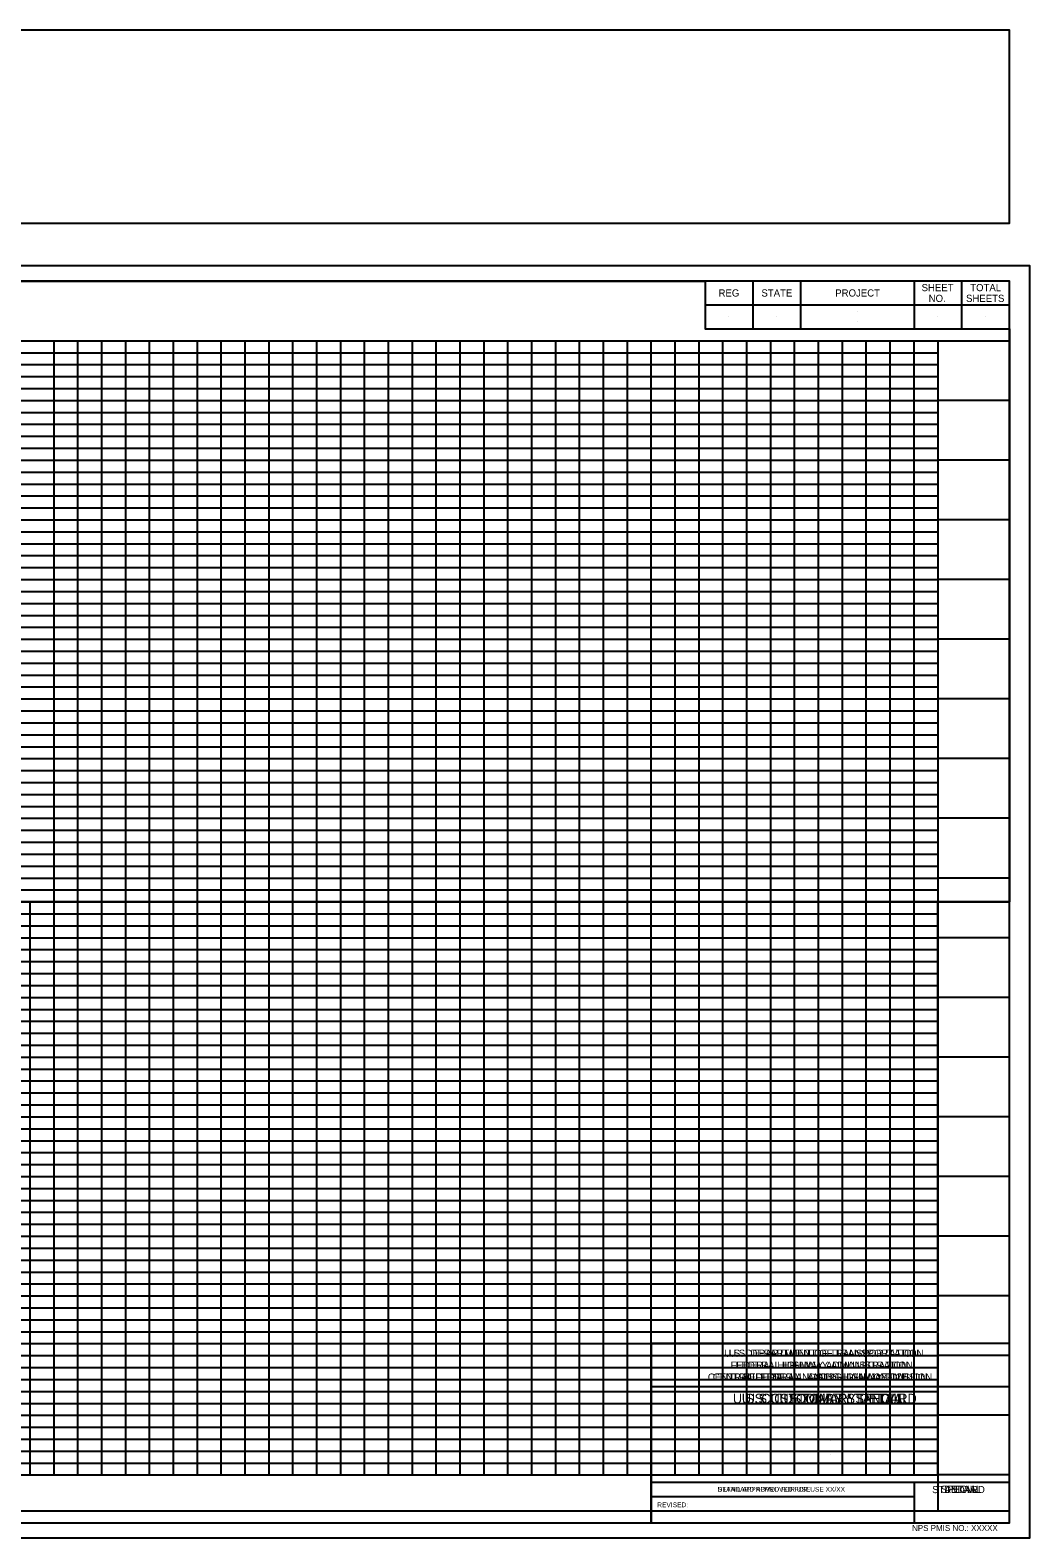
# Model space of a CAD drawing. Extents: x -87 to 1577, y -13 to 1250.
# Drawn here: x 740 to 1577, y -13 to 1250 of the extents above; entities that cross this region are included whole.
import ezdxf

# ---------------------------------------------------------------- set-up
doc = ezdxf.new("R2010")
doc.units = 0
for name, color, linetype in [('D_CFL_Clip_Boundary_1', 7, 'Continuous'), ('D_CFL_Clip_Boundary_2', 7, 'Continuous'), ('D_CFL_Sheet_Border_ PlotShape', 7, 'Continuous'), ('D_CFL_Sheet_Border_Base', 7, 'Continuous'), ('D_CFL_Sheet_Border_Box', 7, 'Continuous'), ('D_CFL_Sheet_Border_Detail', 7, 'Continuous'), ('D_CFL_Sheet_Border_General', 7, 'Continuous'), ('D_CFL_Sheet_Border_NPS_Pkg', 7, 'Continuous'), ('D_CFL_Sheet_Border_Plan_Plan', 7, 'Continuous'), ('D_CFL_Sheet_Border_PnP', 7, 'Continuous'), ('D_CFL_Sheet_Border_Profile', 7, 'Continuous'), ('D_CFL_Sheet_Border_Project_Info', 7, 'Continuous'), ('D_CFL_Sheet_Border_Special', 7, 'Continuous'), ('D_CFL_Sheet_Border_Standard', 7, 'Continuous')]:
    doc.layers.add(name, color=color, linetype=linetype)

msp = doc.modelspace()

# ---------------------------------------------------------------- linework, layer by layer
at = {"layer": 'D_CFL_Clip_Boundary_1'}
msp.add_lwpolyline([(0, 520), (0, 1040), (1305, 1040), (1305, 1000), (1560, 1000), (1560, 520)], close=True, dxfattribs=at)
at = {"layer": 'D_CFL_Clip_Boundary_2'}
msp.add_lwpolyline([(1500, 520), (60, 520), (60, 40), (1500, 40)], close=True, dxfattribs=at)
at = {"layer": 'D_CFL_Sheet_Border_ PlotShape'}
msp.add_line((1576.9, 1052.6), (1576.9, 1052.6), dxfattribs=at)
msp.add_lwpolyline([(-86.9, -12.7), (1576.9, -12.7), (1576.9, 1052.6), (-86.9, 1052.6)], close=True, dxfattribs=at)
at = {"layer": 'D_CFL_Sheet_Border_Base'}
for p, q in [((1345, 1040), (1345, 1000)), ((1385, 1040), (1385, 1000)), ((1480, 1040), (1480, 1000)), ((1520, 1000), (1520, 1040)), ((1305, 1020), (1560, 1020))]:
    msp.add_line(p, q, dxfattribs=at)
for points in [[(362.6, 1088.6), (1560, 1088.6), (1560, 1250.1), (362.6, 1250.1)], [(0, 0), (1560, 0), (1560, 1040), (0, 1040)]]:
    msp.add_lwpolyline(points, close=True, dxfattribs=at)
msp.add_lwpolyline([(1305, 1040), (1305, 1000), (1560, 1000)], dxfattribs=at)
at = {"layer": 'D_CFL_Sheet_Border_Box'}
for p, q in [((1260, 0), (1260, 114)), ((1260, 114), (1560, 114)), ((1410, 57), (1410, 57))]:
    msp.add_line(p, q, dxfattribs=at)
at = {"layer": 'D_CFL_Sheet_Border_Detail'}
for p, q in [((1260, 114), (1560, 114)), ((1410, 69), (1410, 69)), ((1260, 34), (1560, 34)), ((1480, 34), (1480, 0)), ((1260, 22), (1480, 22))]:
    msp.add_line(p, q, dxfattribs=at)
msp.add_lwpolyline([(1560, 150), (1260, 150), (1260, 0)], dxfattribs=at)
at = {"layer": 'D_CFL_Sheet_Border_General'}
for p, q in [((1260, 114), (1560, 114)), ((1410, 57), (1410, 57))]:
    msp.add_line(p, q, dxfattribs=at)
msp.add_lwpolyline([(1560, 150), (1260, 150), (1260, 0)], dxfattribs=at)
at = {"layer": 'D_CFL_Sheet_Border_Plan_Plan'}
for p, q in [((0, 520), (1560, 520)), ((1260, 0), (1260, 114)), ((1260, 114), (1560, 114)), ((1410, 57), (1410, 57))]:
    msp.add_line(p, q, dxfattribs=at)
at = {"layer": 'D_CFL_Sheet_Border_PnP'}
for p, q in [((0, 520), (1560, 520)), ((740, 39.7), (740, 519.7)), ((760, 39.7), (760, 519.7)), ((780, 40), (780, 520)), ((800, 39.7), (800, 519.7)), ((820, 39.7), (820, 519.7)), ((840, 39.7), (840, 519.7)), ((860, 39.7), (860, 519.7)), ((880, 40), (880, 520)), ((900, 39.7), (900, 519.7)), ((920, 39.7), (920, 519.7)), ((940, 39.7), (940, 519.7)), ((960, 39.7), (960, 519.7)), ((980, 40), (980, 520)), ((1000, 39.7), (1000, 519.7)), ((1020, 39.7), (1020, 519.7)), ((1040, 39.7), (1040, 519.7)), ((1060, 39.7), (1060, 519.7)), ((1080, 40), (1080, 520)), ((1100, 39.7), (1100, 519.7)), ((1120, 39.7), (1120, 519.7)), ((1140, 39.7), (1140, 519.7)), ((1160, 39.7), (1160, 519.7)), ((1180, 40), (1180, 520)), ((1200, 39.7), (1200, 519.7)), ((1220, 39.7), (1220, 519.7)), ((1240, 39.7), (1240, 519.7)), ((1260, 39.7), (1260, 519.7)), ((1280, 40), (1280, 520)), ((1300, 39.7), (1300, 519.7)), ((1320, 39.7), (1320, 519.7)), ((1340, 39.7), (1340, 519.7)), ((1360, 39.7), (1360, 519.7)), ((1380, 40), (1380, 520)), ((1400, 39.7), (1400, 519.7)), ((1420, 39.7), (1420, 519.7)), ((1440, 39.7), (1440, 519.7)), ((1460, 39.7), (1460, 519.7)), ((1480, 40), (1480, 520)), ((1500, 520), (1500, 10)), ((60, 510), (1500, 510)), ((60, 500), (1500, 500)), ((60, 490), (1500, 490)), ((60, 480), (1500, 480)), ((1560, 490), (1500, 490)), ((60, 470), (1500, 470)), ((60, 460), (1500, 460)), ((60, 450), (1500, 450)), ((60, 440), (1500, 440)), ((60, 430), (1500, 430)), ((1560, 440), (1500, 440)), ((60, 420), (1500, 420)), ((60, 410), (1500, 410)), ((60, 400), (1500, 400)), ((60, 390), (1500, 390)), ((60, 380), (1500, 380)), ((1560, 390), (1500, 390)), ((60, 370), (1500, 370)), ((60, 360), (1500, 360)), ((60, 350), (1500, 350)), ((60, 340), (1500, 340)), ((60, 330), (1500, 330)), ((1560, 340), (1500, 340)), ((60, 320), (1500, 320)), ((60, 310), (1500, 310)), ((60, 300), (1500, 300)), ((60, 290), (1500, 290)), ((60, 280), (1500, 280)), ((1560, 290), (1500, 290)), ((60, 270), (1500, 270)), ((60, 260), (1500, 260)), ((60, 250), (1500, 250)), ((60, 240), (1500, 240)), ((1560, 240), (1500, 240)), ((60, 230), (1500, 230)), ((60, 220), (1500, 220)), ((60, 210), (1500, 210)), ((60, 200), (1500, 200)), ((60, 190), (1500, 190)), ((1560, 190), (1500, 190)), ((60, 180), (1500, 180)), ((60, 170), (1500, 170)), ((60, 160), (1500, 160)), ((60, 150), (1500, 150)), ((60, 140), (1500, 140)), ((1560, 140), (1500, 140)), ((60, 130), (1500, 130)), ((60, 120), (1500, 120)), ((60, 110), (1500, 110)), ((60, 100), (1500, 100)), ((60, 90), (1500, 90)), ((1560, 90), (1500, 90)), ((60, 80), (1500, 80)), ((60, 70), (1500, 70)), ((60, 60), (1500, 60)), ((60, 50), (1500, 50)), ((60, 40), (1500, 40)), ((1560, 40), (1500, 40)), ((0, 10), (1560, 10))]:
    msp.add_line(p, q, dxfattribs=at)
at = {"layer": 'D_CFL_Sheet_Border_Profile'}
for p, q in [((0, 990), (1560, 990)), ((760, 40), (760, 990)), ((780, 40), (780, 990)), ((800, 40), (800, 990)), ((820, 40), (820, 990)), ((840, 40), (840, 990)), ((860, 40), (860, 990)), ((880, 40), (880, 990)), ((900, 40), (900, 990)), ((920, 40), (920, 990)), ((940, 40), (940, 990)), ((960, 40), (960, 990)), ((980, 40), (980, 990)), ((1000, 40), (1000, 990)), ((1020, 40), (1020, 990)), ((1040, 40), (1040, 990)), ((1060, 40), (1060, 990)), ((1080, 40), (1080, 990)), ((1100, 40), (1100, 990)), ((1120, 40), (1120, 990)), ((1140, 40), (1140, 990)), ((1160, 40), (1160, 990)), ((1180, 40), (1180, 990)), ((1200, 40), (1200, 990)), ((1220, 40), (1220, 990)), ((1240, 40), (1240, 990)), ((1260, 40), (1260, 990)), ((1280, 40), (1280, 990)), ((1300, 40), (1300, 990)), ((1320, 40), (1320, 990)), ((1340, 40), (1340, 990)), ((1360, 40), (1360, 990)), ((1380, 40), (1380, 990)), ((1400, 40), (1400, 990)), ((1420, 40), (1420, 990)), ((1440, 40), (1440, 990)), ((1460, 40), (1460, 990)), ((1480, 40), (1480, 990)), ((1500, 990), (1500, 10)), ((60, 980), (1500, 980)), ((60, 970), (1500, 970)), ((60, 960), (1500, 960)), ((60, 950), (1500, 950)), ((60, 940), (1500, 940)), ((1560, 940), (1500, 940)), ((60, 930), (1500, 930)), ((60, 920), (1500, 920)), ((60, 910), (1500, 910)), ((60, 900), (1500, 900)), ((60, 890), (1500, 890)), ((1560, 890), (1500, 890)), ((60, 880), (1500, 880)), ((60, 870), (1500, 870)), ((60, 860), (1500, 860)), ((60, 850), (1500, 850)), ((60, 840), (1500, 840)), ((1560, 840), (1500, 840)), ((60, 830), (1500, 830)), ((60, 820), (1500, 820)), ((60, 810), (1500, 810)), ((60, 800), (1500, 800)), ((60, 790), (1500, 790)), ((1560, 790), (1500, 790)), ((60, 780), (1500, 780)), ((60, 770), (1500, 770)), ((60, 760), (1500, 760)), ((60, 750), (1500, 750)), ((60, 740), (1500, 740)), ((1560, 740), (1500, 740)), ((60, 730), (1500, 730)), ((60, 720), (1500, 720)), ((60, 710), (1500, 710)), ((60, 700), (1500, 700)), ((60, 690), (1500, 690)), ((1560, 690), (1500, 690)), ((60, 680), (1500, 680)), ((60, 670), (1500, 670)), ((60, 660), (1500, 660)), ((60, 650), (1500, 650)), ((60, 640), (1500, 640)), ((1560, 640), (1500, 640)), ((60, 630), (1500, 630)), ((60, 620), (1500, 620)), ((60, 610), (1500, 610)), ((60, 600), (1500, 600)), ((60, 590), (1500, 590)), ((1560, 590), (1500, 590)), ((60, 580), (1500, 580)), ((60, 570), (1500, 570)), ((60, 560), (1500, 560)), ((60, 550), (1500, 550)), ((60, 540), (1500, 540)), ((1560, 540), (1500, 540)), ((60, 530), (1500, 530)), ((60, 520), (1500, 520)), ((60, 510), (1500, 510)), ((60, 500), (1500, 500)), ((60, 490), (1500, 490)), ((60, 480), (1500, 480)), ((1560, 490), (1500, 490)), ((60, 470), (1500, 470)), ((60, 460), (1500, 460)), ((60, 450), (1500, 450)), ((60, 440), (1500, 440)), ((60, 430), (1500, 430)), ((1560, 440), (1500, 440)), ((60, 420), (1500, 420)), ((60, 410), (1500, 410)), ((60, 400), (1500, 400)), ((60, 390), (1500, 390)), ((60, 380), (1500, 380)), ((1560, 390), (1500, 390)), ((60, 370), (1500, 370)), ((60, 360), (1500, 360)), ((60, 350), (1500, 350)), ((60, 340), (1500, 340)), ((60, 330), (1500, 330)), ((1560, 340), (1500, 340)), ((60, 320), (1500, 320)), ((60, 310), (1500, 310)), ((60, 300), (1500, 300)), ((60, 290), (1500, 290)), ((60, 280), (1500, 280)), ((1560, 290), (1500, 290)), ((60, 270), (1500, 270)), ((60, 260), (1500, 260)), ((60, 250), (1500, 250)), ((60, 240), (1500, 240)), ((1560, 240), (1500, 240)), ((60, 230), (1500, 230)), ((60, 220), (1500, 220)), ((60, 210), (1500, 210)), ((60, 200), (1500, 200)), ((60, 190), (1500, 190)), ((1560, 190), (1500, 190)), ((60, 180), (1500, 180)), ((60, 170), (1500, 170)), ((60, 160), (1500, 160)), ((60, 150), (1500, 150)), ((60, 140), (1500, 140)), ((1560, 140), (1500, 140)), ((60, 130), (1500, 130)), ((60, 120), (1500, 120)), ((60, 110), (1500, 110)), ((60, 100), (1500, 100)), ((60, 90), (1500, 90)), ((1560, 90), (1500, 90)), ((60, 80), (1500, 80)), ((60, 70), (1500, 70)), ((60, 60), (1500, 60)), ((60, 50), (1500, 50)), ((60, 40), (1500, 40)), ((1560, 40), (1500, 40)), ((0, 10), (1560, 10))]:
    msp.add_line(p, q, dxfattribs=at)
at = {"layer": 'D_CFL_Sheet_Border_Project_Info'}
for p, q in [((1432.5, 1014.7), (1432.5, 1014.7)), ((1325, 1010), (1325, 1010)), ((1365, 1010), (1365, 1010)), ((1432.5, 1005.7), (1432.5, 1005.7)), ((1500, 1010), (1500, 1010)), ((1540, 1010), (1540, 1010))]:
    msp.add_line(p, q, dxfattribs=at)
at = {"layer": 'D_CFL_Sheet_Border_Special'}
for p, q in [((1260, 114), (1560, 114)), ((1410, 69), (1410, 69)), ((1260, 34), (1560, 34)), ((1480, 34), (1480, 0)), ((1260, 22), (1480, 22))]:
    msp.add_line(p, q, dxfattribs=at)
msp.add_lwpolyline([(1560, 150), (1260, 150), (1260, 0)], dxfattribs=at)
at = {"layer": 'D_CFL_Sheet_Border_Standard'}
for p, q in [((1260, 114), (1560, 114)), ((1410, 69), (1410, 69)), ((1260, 34), (1560, 34)), ((1480, 34), (1480, 0)), ((1260, 22), (1480, 22))]:
    msp.add_line(p, q, dxfattribs=at)
msp.add_lwpolyline([(1560, 150), (1260, 150), (1260, 0)], dxfattribs=at)

# ---------------------------------------------------------------- texts
at = {"layer": 'D_CFL_Sheet_Border_Base'}
for s, p in [('SHEET', (1486.3, 1031.5)), ('TOTAL', (1527, 1031.5)), ('REG', (1316.3, 1027)), ('STATE', (1352.2, 1027)), ('PROJECT', (1414, 1027)), ('NO.', (1492.2, 1022.5)), ('SHEETS', (1523.5, 1022.5))]:
    msp.add_text(s, height=6, dxfattribs=at).set_placement(p)
at = {"layer": 'D_CFL_Sheet_Border_Detail'}
for s, height, p in [('U.S. DEPARTMENT OF TRANSPORTATION', 6, (1321, 139)), ('FEDERAL HIGHWAY ADMINISTRATION', 6, (1326.4, 129)), ('CENTRAL FEDERAL LANDS HIGHWAY DIVISION', 6, (1307.3, 119)), ('U.S. CUSTOMARY DETAIL', 8, (1339.1, 100)), ('DETAIL APPROVED FOR USE', 4, (1315.5, 26)), ('DETAIL', 6, (1505.1, 25)), ('REVISED:                                                 ', 4, (1265, 13))]:
    msp.add_text(s, height=height, dxfattribs=at).set_placement(p)
at = {"layer": 'D_CFL_Sheet_Border_General'}
for s, p in [('U.S. DEPARTMENT OF TRANSPORTATION', (1325.2, 139)), ('FEDERAL HIGHWAY ADMINISTRATION', (1330.6, 129)), ('CENTRAL FEDERAL LANDS HIGHWAY DIVISION', (1311.5, 119))]:
    msp.add_text(s, height=6, dxfattribs=at).set_placement(p)
at = {"layer": 'D_CFL_Sheet_Border_NPS_Pkg'}
msp.add_text('NPS PMIS NO.: XXXXX ', height=5, dxfattribs=at).set_placement((1478.3, -6.9))
at = {"layer": 'D_CFL_Sheet_Border_Special'}
for s, height, p in [('U.S. DEPARTMENT OF TRANSPORTATION', 6, (1325.2, 139)), ('FEDERAL HIGHWAY ADMINISTRATION', 6, (1330.6, 129)), ('CENTRAL FEDERAL LANDS HIGHWAY DIVISION', 6, (1311.5, 119)), ('U.S. CUSTOMARY SPECIAL', 8, (1335.8, 100)), ('SPECIAL', 6, (1502.4, 25))]:
    msp.add_text(s, height=height, dxfattribs=at).set_placement(p)
at = {"layer": 'D_CFL_Sheet_Border_Standard'}
for s, height, p in [('U.S. DEPARTMENT OF TRANSPORTATION', 6, (1325.2, 139)), ('FEDERAL HIGHWAY ADMINISTRATION', 6, (1330.6, 129)), ('FEDERAL LANDS HIGHWAY OFFICE', 6, (1337.2, 119)), ('U.S. CUSTOMARY STANDARD', 8, (1328.3, 100)), ('STANDARD APPROVED FOR USE XX/XX', 4, (1315.7, 26)), ('STANDARD', 6, (1495.1, 24.8)), ('REVISED:                                                 ', 4, (1265, 13))]:
    msp.add_text(s, height=height, dxfattribs=at).set_placement(p)

doc.saveas('drawing.dxf')
